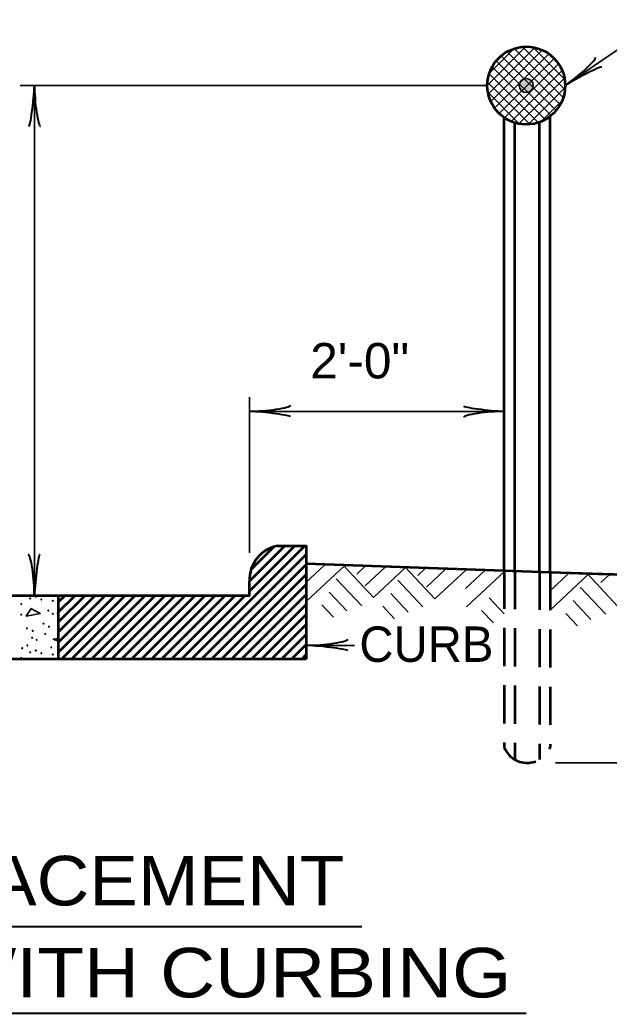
# Model space of a CAD drawing. Extents: x -54 to 626, y -41 to 399.
# Drawn here: x 78 to 119.6, y 80.9 to 151.1 of the extents above; entities that cross this region are included whole.
import ezdxf
from ezdxf.enums import TextEntityAlignment as Align

# ---------------------------------------------------------------- set-up
doc = ezdxf.new("R2010")
doc.units = 0
doc.header["$LTSCALE"] = 0.9
doc.linetypes.add('MEDIUM_DASHED', pattern=[4.5, 3, -1.5])
doc.layers.add('1', color=7, linetype='Continuous', lineweight=35)

msp = doc.modelspace()

# ---------------------------------------------------------------- hatches: boundary and pattern name
at = {"layer": '1'}
msp.add_hatch(color=256, dxfattribs=at).paths.add_polyline_path([(114.2362, 146.4421, 1), (113.2362, 146.4421, 1)])

# ---------------------------------------------------------------- linework, layer by layer
for p, q in [((110.9872, 146.4705), (113.7066, 149.1899)), ((111.0565, 145.8327), (114.3448, 149.121)), ((111.1374, 147.3278), (112.8513, 149.0418)), ((111.2372, 145.3063), (114.872, 148.9411)), ((116.1302, 145.0942), (112.3892, 148.8351)), ((116.3447, 145.5867), (112.8806, 149.0508)), ((116.4688, 146.1697), (113.4627, 149.1758)), ((116.4424, 146.9032), (114.1972, 149.1484)), ((111.4933, 144.8553), (115.3237, 148.6857)), ((115.4856, 144.3245), (111.6194, 148.1907)), ((111.8205, 144.4754), (115.7027, 148.3576)), ((115.8398, 144.6773), (111.9707, 148.5465)), ((115.823, 148.2297), (115.5258, 148.5269)), ((115.0645, 144.0384), (111.3317, 147.7713)), ((112.2102, 144.158), (116.021, 147.9688)), ((112.6703, 143.911), (116.2668, 147.5076)), ((113.9826, 143.7062), (111.0014, 146.6873)), ((114.5696, 143.8263), (111.1208, 147.2752)), ((113.2137, 143.7473), (116.4312, 146.9647)), ((110.9862, 146.4421), (77.9862, 146.4421)), ((78.9862, 146.4421), (78.9862, 110.4283)), ((113.2393, 143.7423), (111.0366, 145.9451)), ((113.8741, 143.7005), (116.4784, 146.3049)), ((114.7854, 143.9048), (116.2769, 145.3963)), ((94.1902, 113.4283), (94.1902, 124.4283)), ((94.1902, 123.4283), (112.1817, 123.4283)), ((99.5081, 112.5922), (98.1427, 111.3191)), ((100.9272, 112.5427), (98.2173, 110.0157)), ((100.8272, 112.5462), (102.9492, 110.2707)), ((102.3463, 112.4931), (101.7664, 111.933)), ((103.7854, 112.4428), (102.3581, 111.1118)), ((105.2046, 112.3932), (102.9492, 110.2707)), ((105.2046, 112.3932), (107.2686, 110.1799)), ((106.6238, 112.3438), (106.0859, 111.8422)), ((108.0628, 112.2935), (106.6976, 111.0203)), ((100.314, 111.6035), (102.1087, 109.6997)), ((109.482, 112.2439), (107.2686, 110.1799)), ((110.8012, 112.1978), (109.4359, 110.9248)), ((112.2203, 112.1483), (109.5105, 109.6213)), ((116.7495, 111.9901), (115.4317, 110.7612)), ((118.1686, 111.9406), (115.4317, 109.3883)), ((118.0687, 111.9441), (120.1906, 109.6686)), ((119.5877, 111.891), (119.0078, 111.3309)), ((104.6535, 111.512), (106.4282, 109.6089)), ((117.5554, 111.0014), (119.3501, 109.0976)), ((99.8208, 110.6601), (101.0553, 109.3362)), ((104.1602, 110.5686), (105.3948, 109.2447)), ((111.1139, 110.2657), (112.1817, 109.1208)), ((99.289, 109.7582), (100.1192, 108.8886)), ((103.6085, 109.6673), (104.4379, 108.7778)), ((117.0622, 110.058), (118.2968, 108.7342)), ((110.5822, 109.3637), (111.4123, 108.4942)), ((116.5304, 109.1561), (117.3606, 108.2866)), ((98.2503, 106.8945), (101.6078, 106.8945)), ((115.8067, 98.5938), (130.8067, 98.5938))]:
    msp.add_line(p, q, dxfattribs=at)
at = {"layer": '1', "lineweight": 53}
for p, q in [((112.1817, 112.1897), (112.1817, 144.1737)), ((114.6817, 112.1024), (114.6817, 143.8597)), ((115.4317, 112.0762), (115.4317, 144.2769)), ((112.9317, 112.1635), (112.9317, 143.8124)), ((90.0902, 105.9283), (98.0902, 113.9283)), ((94.1902, 110.7354), (97.3832, 113.9283)), ((94.1904, 111.4427), (96.676, 113.9283)), ((94.2961, 112.2555), (95.8945, 113.8539)), ((90.7973, 105.9283), (98.1902, 113.3212)), ((91.5044, 105.9283), (98.1902, 112.6142)), ((98.1902, 112.6782), (112.1817, 112.1897)), ((92.2116, 105.9283), (98.1902, 111.907)), ((115.4317, 112.0762), (160.1525, 110.5146)), ((92.9187, 105.9283), (98.1902, 111.1999)), ((9.1902, 110.4283), (80.6902, 110.4283)), ((80.6902, 109.9634), (81.1552, 110.4283)), ((80.6902, 109.2562), (81.8623, 110.4283)), ((80.6902, 108.5492), (82.5694, 110.4283)), ((80.6902, 107.8421), (83.2765, 110.4283)), ((80.6902, 107.1349), (83.9837, 110.4283)), ((80.6902, 106.4278), (84.6907, 110.4283)), ((80.8978, 105.9283), (85.3978, 110.4283)), ((81.6049, 105.9283), (86.1049, 110.4283)), ((82.3121, 105.9283), (86.8121, 110.4283)), ((83.0192, 105.9283), (87.5192, 110.4283)), ((83.7262, 105.9283), (88.2262, 110.4283)), ((84.4334, 105.9283), (88.9334, 110.4283)), ((85.1405, 105.9283), (89.6405, 110.4283)), ((85.8476, 105.9283), (90.3476, 110.4283)), ((86.5547, 105.9283), (91.0547, 110.4283)), ((87.2618, 105.9283), (91.7618, 110.4283)), ((87.9689, 105.9283), (92.4689, 110.4283)), ((88.676, 105.9283), (93.176, 110.4283)), ((89.3832, 105.9283), (93.8832, 110.4283)), ((93.6257, 105.9283), (98.1902, 110.4928)), ((94.3329, 105.9283), (98.1902, 109.7857)), ((95.04, 105.9283), (98.1902, 109.0786)), ((95.7471, 105.9283), (98.1902, 108.3715)), ((96.4542, 105.9283), (98.1902, 107.6644)), ((97.1613, 105.9283), (98.1902, 106.9573)), ((97.8684, 105.9283), (98.1902, 106.2502)), ((80.6902, 105.9283), (9.1902, 105.9283))]:
    msp.add_line(p, q, dxfattribs=at)
at = {"layer": '1', "linetype": 'MEDIUM_DASHED', "lineweight": 53}
for p, q in [((112.1817, 112.1897), (112.1817, 99.6897)), ((112.9317, 112.1635), (112.9317, 98.8279)), ((114.6817, 112.1024), (114.6817, 98.8279)), ((115.4317, 112.0762), (115.4317, 99.6897))]:
    msp.add_line(p, q, dxfattribs=at)
at = {"layer": '1', "lineweight": 40}
for p, q in [((34.0568, 87.0277), (102.1171, 87.0277)), ((23.3503, 80.9192), (113.7321, 80.9192))]:
    msp.add_line(p, q, dxfattribs=at)
at = {"layer": '1'}
for points in [[(116.4862, 146.4421), (123.2822, 151.0822), (126.5517, 151.0822)], [(78.7328, 109.4977), (79.3928, 109.1377), (78.4128, 108.9577), (78.7728, 109.5177)], [(80.6902, 107.3813), (80.3128, 107.3377), (80.6902, 107.2046)]]:
    msp.add_lwpolyline(points, dxfattribs=at)
at = {"layer": '1', "lineweight": 53}
for points in [[(96.1902, 113.9283), (98.1902, 113.9283), (98.1902, 105.9283)], [(98.1902, 112.6782), (115.4317, 112.0762), (123.6242, 111.7901)], [(98.1902, 105.9283), (80.6902, 105.9283), (80.6902, 108.428), (80.6902, 110.4283), (94.1902, 110.4283), (94.1902, 111.4283)]]:
    msp.add_lwpolyline(points, dxfattribs=at)
msp.add_circle((113.7362, 146.4421), 2.75, dxfattribs=at)
at = {"layer": '1'}
for centre, radius in [((113.7362, 146.4421), 0.5), ((78.6811, 110.2075), 0.0265), ((79.0787, 110.3353), 0.0265), ((79.4763, 110.1412), 0.0265), ((78.0583, 109.8098), 0.0265), ((80.2847, 110.0484), 0.0265), ((78.0582, 109.0674), 0.0265), ((79.9667, 109.3591), 0.0265), ((80.2847, 109.1205), 0.0265), ((80.6293, 109.1602), 0.0265), ((78.4558, 108.0996), 0.0265), ((79.6221, 108.4311), 0.0265), ((80.0197, 108.219), 0.0265), ((78.8269, 107.4368), 0.0265), ((78.8667, 107.9272), 0.0265), ((79.7414, 107.7019), 0.0265), ((78.1245, 106.6943), 0.0265), ((78.4823, 106.8932), 0.0265), ((79.145, 107.2909), 0.0265), ((80.1787, 106.7606), 0.0265), ((78.0583, 106.0098), 0.0265), ((78.6811, 106.4075), 0.0265), ((79.0787, 106.5353), 0.0265), ((79.4763, 106.3412), 0.0265), ((80.2847, 106.2484), 0.0265)]:
    msp.add_circle(centre, radius, dxfattribs=at)
at = {"layer": '1', "lineweight": 53}
msp.add_arc((96.5971, 111.5529), 2.41, 99.71788, 182.9625, dxfattribs=at)
at = {"layer": '1'}
msp.add_arc((80.7089, 108.4311), 0.0265, 134.79633, 225.20367, dxfattribs=at)
at = {"layer": '1', "linetype": 'MEDIUM_DASHED', "lineweight": 53}
msp.add_arc((113.8067, 100.3467), 1.7528, 202.01371, 337.98629, dxfattribs=at)
at = {"layer": '1', "lineweight": 40}
for centre, major_axis, ratio, start_param, end_param in [((117.2316, 147.2856), (-1.3867, -1.1359), 0.122415, 0.8963533, 3.1415927), ((117.5309, 146.8992), (-1.5496, -0.8454), 0.07063, 3.1407148, 5.41811), ((78.7746, 145.3216), (0.1757, 1.7565), 0.07063, 3.1407148, 5.41811), ((78.7746, 145.3216), (0.1757, 1.7565), 0.07063, 3.1407148, 5.41811), ((79.2625, 145.3509), (-0.1562, 1.7857), 0.122415, 0.8963533, 3.1415927), ((79.2625, 145.3509), (-0.1562, 1.7857), 0.122415, 0.8963533, 3.1415927), ((95.2814, 123.7046), (-1.7857, -0.1562), 0.122415, 0.8963533, 3.1415927), ((95.2814, 123.7046), (-1.7857, -0.1562), 0.122415, 0.8963533, 3.1415927), ((111.0612, 123.6399), (1.7565, -0.1757), 0.07063, 3.1407148, 5.41811), ((95.3108, 123.2167), (-1.7565, 0.1757), 0.07063, 3.1407148, 5.41811), ((95.3108, 123.2167), (-1.7565, 0.1757), 0.07063, 3.1407148, 5.41811), ((111.0905, 123.152), (1.7857, 0.1562), 0.122415, 0.8963533, 3.1415927), ((78.71, 111.5195), (0.1562, -1.7857), 0.122415, 0.8963533, 3.1415927), ((79.1979, 111.5488), (-0.1757, -1.7565), 0.07063, 3.1407148, 5.41811), ((99.3708, 106.6829), (-1.7565, 0.1757), 0.07063, 3.1407148, 5.41811), ((99.3415, 107.1708), (-1.7857, -0.1562), 0.122415, 0.8963533, 3.1415927)]:
    msp.add_ellipse(centre, major_axis=major_axis, ratio=ratio, start_param=start_param, end_param=end_param, dxfattribs=at)

# ---------------------------------------------------------------- texts
at = {"layer": '1', "width": 1.05}
msp.add_text('2\'-0"', height=2.5, dxfattribs=at).set_placement((98.4723, 125.7566))
at = {"layer": '1'}
msp.add_text('CURB', height=2.5, dxfattribs=at).set_placement((101.9446, 105.7318))
for s, width, p in [('DELINEATOR PLACEMENT', 1.1, (67.982, 88.5277)), ('TYPICAL SECTION WITH CURBING', 1.15, (67.982, 82.0277))]:
    msp.add_text(s, height=3.5, dxfattribs=dict(at, width=width)).set_placement(p, align=Align.CENTER)

doc.saveas('drawing.dxf')
